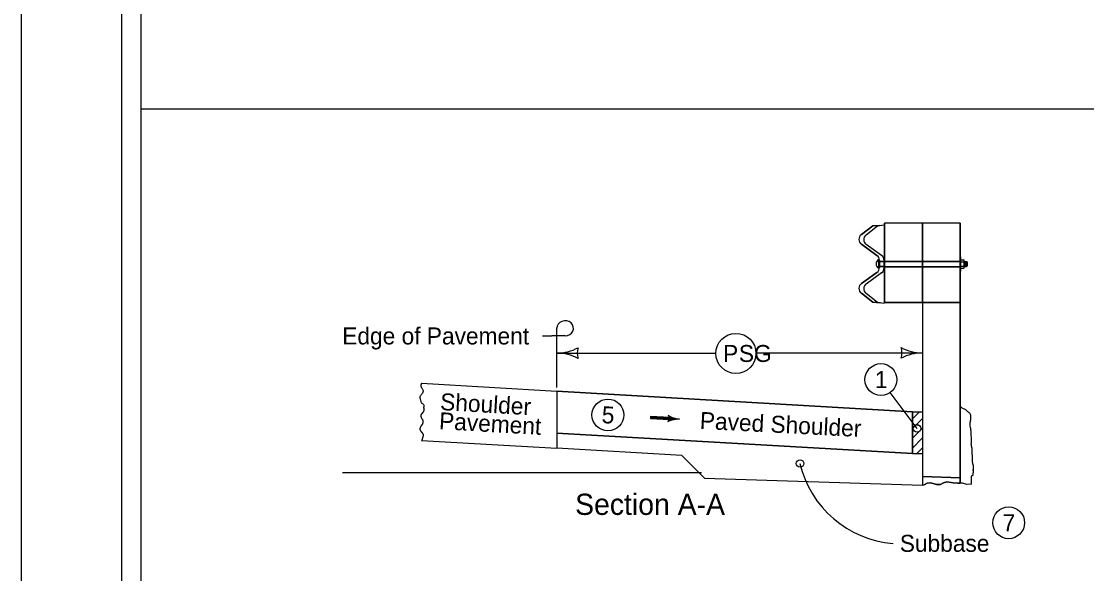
# Model space of a CAD drawing. Extents: x 10038 to 81668, y 7924 to 11018.
# Drawn here: x 10038 to 11041, y 8921 to 9442 of the extents above; entities that cross this region are included whole.
import ezdxf

# ---------------------------------------------------------------- set-up
doc = ezdxf.new("R2010")
doc.units = 0
for name, color, linetype in [('dsnCellElements', 7, 'Continuous'), ('DsnShtMinorGrid05', 7, 'Continuous'), ('DsnShtMinorGrid06', 7, 'Continuous'), ('DsnShtMinorGrid07', 7, 'Continuous'), ('DsnShtMinorGrid09', 7, 'Continuous'), ('DsnShtMinorGrid10', 7, 'Continuous'), ('DsnShtMinorGrid11', 7, 'Continuous'), ('DsnShtMinorGrid14', 7, 'Continuous'), ('Level 60', 7, 'Continuous'), ('SheetBorder', 7, 'Continuous')]:
    doc.layers.add(name, color=color, linetype=linetype)

msp = doc.modelspace()

# ---------------------------------------------------------------- linework, layer by layer
at = {"layer": 'dsnCellElements'}
msp.add_lwpolyline([(10037.7, 8180), (13358.6, 8180), (13358.6, 10373.4), (10037.7, 10373.4)], close=True, dxfattribs=at)
at = {"layer": 'DsnShtMinorGrid05'}
for p, q in [((10542.3, 9128.9), (10692.1, 9128.9)), ((10729.9, 9129), (10886.7, 9129))]:
    msp.add_line(p, q, dxfattribs=at)
msp.add_circle((10711, 9128.5), 18.9, dxfattribs=at)
for centre, radius, start, end in [((10542.3, 9171.4), 42.5, 270, 298.0725), ((10542.3, 9086.4), 42.5, 61.9275, 90), ((10577.9, 9128.9), 16.4, 162.2666, 197.7334), ((10851, 9129), 16.4, 342.2666, 17.7333), ((10886.7, 9171.5), 42.5, 241.9275, 270), ((10886.7, 9086.5), 42.5, 90, 118.0725), ((10866.6, 9047), 97.8, 193.077, 265.558)]:
    msp.add_arc(centre, radius, start, end, dxfattribs=at)
at = {"layer": 'DsnShtMinorGrid06'}
msp.add_line((10150.3, 9926.7), (10150.3, 8316.7), dxfattribs=at)
at = {"layer": 'DsnShtMinorGrid07'}
for p, q in [((10829.4, 9231.4), (10843.9, 9220.9)), ((10843.9, 9204.9), (10829.4, 9194.5))]:
    msp.add_line(p, q, dxfattribs=at)
for points in [[(10833.6, 9240.3), (10833.6, 9240.3), (10844.4, 9248.7), (10846.3, 9249), (10839.9, 9248.9), (10829.2, 9240.5)], [(10886.7, 9215.6), (10886.7, 9251.2), (10851.1, 9251.2), (10851.1, 9215.6), (10851.1, 9215.6), (10886.7, 9215.6)], [(10922.2, 9215.6), (10922.2, 9219.6), (10922.2, 9251.2), (10886.7, 9251.2), (10886.7, 9215.6), (10922.2, 9215.6)], [(10848.3, 9220.7), (10848.3, 9220.7), (10833.8, 9231.2), (10833.8, 9231.1)], [(10846.3, 9216.3), (10846.3, 9215.2), (10850.7, 9215.2), (10850.7, 9216.1), (10850.7, 9216.1)], [(10851.1, 9215.2), (10851.1, 9210.6), (10851.1, 9210.6), (10886.7, 9210.6), (10886.7, 9215.2), (10851.1, 9215.2), (10851.1, 9215.2)], [(10922.2, 9210.6), (10922.2, 9215.2), (10886.7, 9215.2), (10886.7, 9210.6), (10922.2, 9210.6)], [(10833.8, 9194.2), (10833.8, 9194.2), (10848.3, 9204.7), (10848.3, 9204.7)], [(10850.7, 9209.3), (10850.7, 9209.3), (10850.7, 9210.6), (10846.3, 9210.6), (10846.3, 9209.5), (10846.3, 9210.6), (10846.3, 9210.6), (10846.3, 9209.5)], [(10851.1, 9210.2), (10851.1, 9176.6), (10886.7, 9176.6), (10886.7, 9210.2), (10851.1, 9210.2)], [(10922.2, 9176.6), (10922.2, 9206.2), (10922.2, 9210.2), (10886.7, 9210.2), (10886.7, 9176.6), (10922.2, 9176.6)], [(10829.2, 9185.3), (10839.9, 9176.9), (10847, 9176.3), (10844.4, 9176.7), (10833.6, 9185.1), (10833.6, 9185.1)], [(10922.2, 9011.3), (10922.2, 9176.6), (10886.7, 9176.6), (10886.7, 9073.6), (10886.7, 9066.9), (10886.7, 9066.9), (10886.7, 9066.9), (10886.7, 9057.7), (10886.7, 9057.7), (10886.7, 9057.7), (10886.7, 9048.6), (10886.7, 9048.6), (10886.7, 9048.6), (10886.7, 9041.6), (10886.7, 9012.4), (10922.2, 9011.3)], [(10922.2, 9011.3), (10886.7, 9012.4), (10886.7, 9004.4), (10888.5, 9004.6), (10891.2, 9006.2), (10894.5, 9006.7), (10900.1, 9005.1), (10903.8, 9004.9), (10906.5, 9006.7), (10909.6, 9007.4), (10915.8, 9006.6), (10920, 9006.2), (10922.2, 9006.2), (10922.2, 9011.3)]]:
    msp.add_lwpolyline(points, dxfattribs=at)
msp.add_lwpolyline([(10850.7, 9215.2), (10846.3, 9215.2), (10846.3, 9211.8), (10846.3, 9212.9), (10846.3, 9210.6), (10850.7, 9210.6)], close=True, dxfattribs=at)
for centre, start, end in [((10832.6, 9236), 127.75, 234.6909), ((10837.1, 9235.8), 127.75, 234.6909), ((10840.6, 9216.3), 360, 54.691), ((10845, 9216.1), 360, 54.691), ((10840.6, 9209.5), 305.309, 0), ((10845, 9209.3), 305.309, 0), ((10832.6, 9189.8), 125.3091, 232.25), ((10837.1, 9189.6), 125.3091, 232.25)]:
    msp.add_arc(centre, 5.68, start, end, dxfattribs=at)
at = {"layer": 'DsnShtMinorGrid09'}
for centre, radius in [((10847.6, 9103.9), 15), ((10590.4, 9070.5), 15), ((10881.7, 9057.8), 3.58), ((10968, 8968.9), 15)]:
    msp.add_circle(centre, radius, dxfattribs=at)
at = {"layer": 'DsnShtMinorGrid10'}
for p, q in [((10528.9, 9145), (10537.6, 9145)), ((10550.1, 9145), (10537.6, 9145)), ((10542.3, 9132.2), (10542.3, 9153.1)), ((10542.3, 9096.3), (10542.3, 9132.2)), ((10648.6, 9067.2), (10630.4, 9068.2)), ((10648.5, 9066.2), (10648.5, 9066.2)), ((10648.7, 9068.2), (10648.7, 9068.2))]:
    msp.add_line(p, q, dxfattribs=at)
for points in [[(10648.7, 9068.1), (10630.5, 9069.1), (10630.4, 9067.3), (10648.5, 9066.2), (10648.6, 9067.8), (10630.7, 9068.9), (10630.7, 9067.4), (10648.2, 9066.5), (10648.3, 9067.6), (10631, 9068.7), (10630.9, 9067.7), (10647.9, 9066.7), (10648, 9067.4), (10631.1, 9068.4), (10631.1, 9067.9), (10647.7, 9066.9)], [(10648.3, 9069.4), (10649, 9068.2), (10648.9, 9066.5), (10648.2, 9065.1), (10650.9, 9066), (10654.1, 9066.7), (10655, 9066.8), (10652.8, 9067.3), (10649.6, 9068.6), (10648.6, 9069.1), (10648.7, 9065.6), (10653.7, 9066.8), (10649, 9068.4), (10649.1, 9066), (10652.5, 9066.9), (10649.5, 9067.8), (10649.2, 9066.4), (10651.4, 9066.9), (10649.8, 9067.4), (10649.7, 9066.7), (10650.4, 9066.9)]]:
    msp.add_lwpolyline(points, dxfattribs=at)
for centre, major_axis, start_param, end_param in [((10550.1, 9152.2), (-7.81, 0), 1.570796, 6.283185), ((10644.9, 9067.4), (3.88, 0), 5.202895, 7.237436), ((10657.1, 9046.4), (22.2, 0), 1.537172, 2.061295), ((10659.9, 9086.8), (-22.2, 0), 0.954258, 1.478381)]:
    msp.add_ellipse(centre, major_axis=major_axis, ratio=0.913811, start_param=start_param, end_param=end_param, dxfattribs=at)
at = {"layer": 'DsnShtMinorGrid11'}
for p, q in [((12305.9, 9358.7), (10150.3, 9358.7)), ((10881.7, 9057.8), (10856.3, 9091.7))]:
    msp.add_line(p, q, dxfattribs=at)
at = {"layer": 'DsnShtMinorGrid14'}
msp.add_circle((10771.4, 9024.8), 3.54, dxfattribs=at)
at = {"layer": 'Level 60'}
for p, q in [((10829.2, 9240.5), (10839.9, 9248.9)), ((10833.6, 9240.3), (10844.4, 9248.7)), ((10839.9, 9248.9), (10846.3, 9249)), ((10844.4, 9248.7), (10850.7, 9249.8)), ((10922.2, 9251.2), (10851.1, 9251.2)), ((10851.1, 9176.6), (10851.1, 9251.2)), ((10886.7, 9176.6), (10886.7, 9251.2)), ((10922.2, 9251.2), (10922.2, 9006.2)), ((10843.9, 9220.9), (10829.4, 9231.4)), ((10848.3, 9220.7), (10833.8, 9231.2)), ((10845.5, 9208.8), (10845.5, 9216.9)), ((10845.5, 9215.2), (10850.9, 9215.2)), ((10846.3, 9209.5), (10846.3, 9216.3)), ((10846.4, 9215.2), (10851.1, 9215.2)), ((10850.7, 9212.7), (10850.7, 9216.1)), ((10851.1, 9215.6), (10922.2, 9215.6)), ((10851.1, 9215.2), (10922.2, 9215.2)), ((10922.2, 9219.5), (10922.9, 9219.5)), ((10922.9, 9206.2), (10922.9, 9219.5)), ((10922.9, 9216.9), (10925.8, 9216.9)), ((10922.9, 9214.9), (10925.8, 9214.9)), ((10926.2, 9209.8), (10926.2, 9215.9)), ((10926.2, 9215.2), (10928.6, 9215.2)), ((10927.1, 9215.2), (10927.1, 9210.5)), ((10927.8, 9215.2), (10927.8, 9210.5)), ((10928.6, 9215.2), (10929, 9214.7)), ((10928.6, 9215.2), (10928.6, 9210.5)), ((10929, 9214.7), (10929, 9211.1)), ((10829.4, 9194.5), (10843.9, 9204.9)), ((10833.8, 9194.2), (10848.3, 9204.7)), ((10845.5, 9210.6), (10851.1, 9210.6)), ((10846.3, 9209.5), (10846.3, 9212.9)), ((10846.3, 9212.9), (10846.3, 9209.5)), ((10850.7, 9209.3), (10850.7, 9212.7)), ((10850.7, 9212.7), (10850.7, 9209.3)), ((10851.1, 9210.6), (10922.2, 9210.6)), ((10851.1, 9210.2), (10922.2, 9210.2)), ((10922.2, 9206.2), (10922.9, 9206.2)), ((10922.9, 9210.9), (10925.8, 9210.9)), ((10922.9, 9208.8), (10925.8, 9208.8)), ((10926.2, 9210.5), (10928.6, 9210.5)), ((10929, 9211.1), (10928.6, 9210.5)), ((10839.9, 9176.9), (10829.2, 9185.3)), ((10844.4, 9176.7), (10833.6, 9185.1)), ((10847, 9176.3), (10839.9, 9176.9)), ((10850.7, 9175.6), (10844.4, 9176.7)), ((10886.7, 9176.6), (10851.1, 9176.6)), ((10886.7, 9176.6), (10886.7, 9004.4)), ((10414.8, 9100.5), (10542.3, 9093.1)), ((10542.3, 9093.1), (10542.3, 9039.1)), ((10542.3, 9093.1), (10877.4, 9073.6)), ((10877.4, 9073.6), (10542.3, 9093.1)), ((10542.3, 9093.1), (10542.3, 9053.5)), ((10877.4, 9066.9), (10884.1, 9073.6)), ((10877.4, 9066.9), (10884.1, 9073.6)), ((10877.4, 9066.9), (10884.1, 9073.6)), ((10877.4, 9066.9), (10884.1, 9073.6)), ((10877.4, 9073.6), (10886.6, 9073.6)), ((10877.4, 9073.6), (10877.4, 9034.2)), ((10877.4, 9034.2), (10877.4, 9073.6)), ((10877.4, 9057.7), (10886.6, 9066.9)), ((10877.4, 9057.7), (10886.6, 9066.9)), ((10877.4, 9057.7), (10886.6, 9066.9)), ((10877.4, 9057.7), (10886.6, 9066.9)), ((10932.2, 9066.9), (10932.2, 9066.9)), ((10877.4, 9048.5), (10886.6, 9057.7)), ((10877.4, 9048.5), (10886.6, 9057.7)), ((10877.4, 9048.5), (10886.6, 9057.7)), ((10877.4, 9048.5), (10886.6, 9057.7)), ((10414.8, 9046.5), (10542.3, 9039.1)), ((10877.4, 9034.2), (10542.3, 9053.5)), ((10542.3, 9053.5), (10877.4, 9034.2)), ((10877.4, 9039.2), (10886.6, 9048.5)), ((10660.1, 9032.3), (10542.3, 9039.1)), ((10877.4, 9034.2), (10886.6, 9034.2)), ((10881.5, 9034.2), (10886.6, 9039.3)), ((10660.1, 9032.3), (10681.4, 9011.1)), ((10340.2, 9016.3), (10678.7, 9016.3)), ((10681.4, 9011.1), (10886.7, 9004.4))]:
    msp.add_line(p, q, dxfattribs=at)
for points in [[(10925.9, 9214.9), (10926, 9214.9), (10926.1, 9215), (10926.1, 9215.3), (10926.2, 9215.6), (10926.2, 9213.6), (10926.1, 9214.1), (10926.1, 9214.5), (10926, 9214.8), (10925.9, 9214.9), (10926, 9214.9), (10926.1, 9215.1), (10926.2, 9215.3), (10926.2, 9215.4), (10926.2, 9213.9), (10926.1, 9214.4), (10926.1, 9214.7), (10925.9, 9214.9), (10926, 9214.9), (10926.1, 9215.1), (10926.2, 9215.3), (10926.2, 9214.2), (10926, 9214.9), (10926.1, 9215.1), (10926.1, 9214.3), (10926, 9214.9), (10926.1, 9215.1), (10926.1, 9214.4), (10926, 9214.8), (10926.1, 9215), (10926.1, 9214.6), (10926, 9214.8), (10926.1, 9214.9), (10926.1, 9214.7), (10926.1, 9214.8), (10926.1, 9214.9)], [(10926.2, 9210.2), (10926.2, 9210.4), (10926.1, 9210.6), (10926, 9210.8), (10925.9, 9210.9), (10926, 9211), (10926.1, 9211.2), (10926.1, 9211.5), (10926.2, 9212.2), (10926.2, 9210.2), (10926.2, 9210.3), (10926.1, 9210.5), (10926.1, 9210.7), (10925.9, 9210.8), (10926, 9210.9), (10926, 9211.1), (10926.1, 9211.6), (10926.2, 9212), (10926.2, 9210.4), (10926.2, 9210.5), (10926.1, 9210.6), (10926, 9210.8), (10926, 9211), (10926.1, 9211.3), (10926.2, 9211.7), (10926.2, 9210.5), (10926.1, 9210.6), (10926, 9210.8), (10926, 9211.1), (10926.1, 9211.3), (10926.1, 9211.5), (10926.1, 9210.6), (10926.1, 9210.7), (10926, 9210.8), (10926.1, 9211.3), (10926.1, 9210.7), (10926, 9210.8), (10926.1, 9211.1), (10926.1, 9210.8), (10926.1, 9210.8), (10926.1, 9210.9), (10926.1, 9210.9)], [(10932.7, 9043), (10932.7, 9042.7), (10932.7, 9042.6), (10932.7, 9042.4), (10932.7, 9042.2), (10932.7, 9042), (10932.7, 9041.8), (10932.7, 9041.5), (10932.7, 9041.3), (10932.8, 9041), (10932.9, 9040.7), (10933.1, 9040.5), (10933.1, 9040.3), (10933.1, 9040.1), (10933.1, 9039.9), (10933.1, 9039.7), (10933.2, 9039.6), (10933.2, 9039.4), (10933.2, 9039.2), (10933.2, 9039), (10933.2, 9038.8), (10933.2, 9038.6), (10933.2, 9038.4), (10933.2, 9038.1), (10933.2, 9037.9), (10933.2, 9037.6), (10933.2, 9037.4), (10933.2, 9037.2), (10933.3, 9037.1), (10933.3, 9036.9), (10933.3, 9036.7), (10933.3, 9036.5), (10933.3, 9036.3), (10933.3, 9036.1), (10933.3, 9035.9), (10933.3, 9035.7), (10933.3, 9035.5), (10933.3, 9035.3), (10933.3, 9035.1), (10933.3, 9034.9), (10933.3, 9034.7), (10933.3, 9034.5), (10933.3, 9034.3), (10933.3, 9034.2), (10933.3, 9034), (10933.3, 9033.8), (10933.3, 9033.6), (10933.4, 9033.5), (10933.4, 9033.3), (10933.4, 9033.1), (10933.5, 9033), (10933.5, 9032.8), (10933.5, 9032.6), (10933.6, 9032.5), (10933.6, 9032.3), (10933.6, 9032.1), (10933.6, 9031.9), (10933.6, 9031.6), (10933.7, 9031.3), (10933.7, 9031.1), (10933.7, 9030.9), (10933.7, 9030.7), (10933.7, 9030.5), (10933.7, 9030.3), (10933.7, 9030.1), (10933.7, 9030), (10933.7, 9029.8), (10933.7, 9029.6), (10933.7, 9029.4), (10933.7, 9029.2), (10933.7, 9029), (10933.7, 9028.8), (10933.7, 9028.6), (10933.7, 9028.4), (10933.7, 9028.2), (10933.7, 9028), (10933.7, 9027.8), (10933.7, 9027.6), (10933.7, 9027.4), (10933.7, 9027.2), (10933.7, 9027), (10933.7, 9026.8), (10933.7, 9026.6), (10933.7, 9026.4), (10933.7, 9026.2), (10933.7, 9026), (10933.7, 9025.8), (10933.7, 9025.7), (10933.8, 9025.6), (10933.8, 9025.3), (10933.8, 9025.1), (10933.9, 9024.9), (10934, 9024.6), (10934, 9024.4), (10934.1, 9024.3), (10934.1, 9024.1), (10934.2, 9024), (10934.3, 9023.9), (10934.3, 9023.7), (10934.3, 9023.5), (10934.3, 9023.3), (10934.4, 9023.2), (10934.4, 9023), (10934.4, 9022.8), (10934.4, 9022.6), (10934.4, 9022.4), (10934.4, 9022.2), (10934.4, 9022), (10934.4, 9021.8), (10934.4, 9021.6), (10934.4, 9021.5), (10934.4, 9021.3), (10934.4, 9021.1), (10934.4, 9020.9), (10934.4, 9020.7), (10934.4, 9020.5), (10934.4, 9020.3), (10934.4, 9020.1), (10934.4, 9019.9), (10934.4, 9019.7), (10934.4, 9019.5), (10934.4, 9019.3), (10934.4, 9019.1), (10934.4, 9018.9), (10934.4, 9018.7), (10934.4, 9018.5), (10934.4, 9018.3), (10934.4, 9018.3), (10934.4, 9018.6), (10934.4, 9018.8), (10934.4, 9019), (10934.4, 9018.8), (10934.4, 9018.6), (10934.4, 9018.4), (10934.4, 9018.2), (10934.4, 9018), (10934.4, 9017.8), (10934.4, 9017.6), (10934.4, 9017.4), (10934.4, 9017.2), (10934.4, 9017.1), (10934.4, 9016.9), (10934.4, 9016.7), (10934.4, 9016.5), (10934.4, 9016.3), (10934.4, 9016.1), (10934.3, 9016), (10934.3, 9015.8), (10934.3, 9015.6), (10934.3, 9015.4), (10934.3, 9015.2), (10934.3, 9015), (10934.3, 9014.8), (10934.3, 9014.6), (10934.3, 9014.4), (10934.3, 9014.2), (10934.3, 9014), (10934.2, 9013.9), (10934.1, 9013.7), (10934, 9013.6), (10933.9, 9013.5), (10933.8, 9013.4), (10933.6, 9013.3), (10933.4, 9013.3), (10933.3, 9013.2), (10933.2, 9013.1), (10933.1, 9013), (10933, 9013), (10932.9, 9012.9), (10932.9, 9012.7), (10932.8, 9012.6), (10932.8, 9012.4), (10932.8, 9012.2), (10932.8, 9012), (10932.8, 9005.2)], [(10932.9, 9005.2), (10928.7, 9005), (10924.6, 9006.2), (10920, 9006.2), (10915.8, 9006.6), (10909.6, 9007.4), (10906.5, 9006.7), (10903.8, 9004.9), (10900.1, 9005.1), (10894.5, 9006.7), (10891.2, 9006.2), (10888.5, 9004.6), (10886.7, 9004.4)]]:
    msp.add_lwpolyline(points, dxfattribs=at)
msp.add_circle((10590.4, 9070.5), 15, dxfattribs=at)
for centre, radius, start, end in [((10832.6, 9236), 5.68, 127.75, 234.6909), ((10837.1, 9235.8), 5.68, 127.75, 234.6909), ((10847.6, 9212.9), 4.54, 117.2029, 242.8461), ((10840.6, 9216.3), 5.68, 360, 54.691), ((10845, 9216.1), 5.68, 360, 54.691), ((10840.6, 9209.5), 5.68, 305.309, 0), ((10845, 9209.3), 5.68, 305.309, 0), ((10832.6, 9189.8), 5.68, 125.3091, 232.25), ((10837.1, 9189.6), 5.68, 125.3091, 232.25)]:
    msp.add_arc(centre, radius, start, end, dxfattribs=at)
for centre in [(10925.8, 9215.9), (10925.8, 9209.8)]:
    msp.add_ellipse(centre, major_axis=(0, -1.01), ratio=0.362258, start_param=6.283156, end_param=9.424748, dxfattribs=at)
for points in [[(10414.8, 9100.5), (10414.3, 9096.9), (10415.3, 9095.4), (10416.2, 9093.1), (10415.6, 9091.1), (10413.7, 9088.7), (10413.2, 9086.8), (10413.7, 9084.5), (10414.6, 9082.1), (10415.6, 9081.4), (10417, 9078.9), (10417, 9078)], [(10415, 9060.9), (10415.2, 9061.2), (10415.4, 9061.4), (10415.8, 9062), (10416, 9062.6), (10416.2, 9062.9), (10416.3, 9063.2), (10416.4, 9063.8), (10416.4, 9064.4), (10416.4, 9065), (10416.3, 9065.3), (10416.3, 9065.4), (10416.3, 9065.6), (10416, 9065.9), (10415.8, 9066.3), (10415.5, 9066.7), (10415.2, 9067.1), (10415.1, 9067.4), (10414.9, 9067.6), (10414.7, 9068.2), (10414.5, 9068.8), (10414.4, 9069.1), (10414.4, 9069.4), (10414.3, 9069.5), (10414.3, 9069.6), (10414.5, 9070.4), (10414.7, 9070.9), (10415, 9071.4), (10415.4, 9072.1), (10415.9, 9072.6), (10416.4, 9073.2), (10416.7, 9073.5), (10416.9, 9073.8), (10417.1, 9074.3), (10417.2, 9074.8), (10417.3, 9075.2), (10417.4, 9075.5), (10417.4, 9075.6), (10417.4, 9075.7), (10417.3, 9076.2), (10417.2, 9076.7), (10417.1, 9076.9), (10417.1, 9077), (10417, 9077.1), (10417, 9077.2), (10417, 9078)], [(10932.7, 9043), (10933, 9045.9), (10932.8, 9050.8), (10932.4, 9056.5), (10931.7, 9061), (10931.9, 9064.3), (10932.4, 9068.5), (10931.7, 9071.6), (10929.5, 9073.6), (10927.5, 9075.3), (10925.3, 9076.4), (10923.1, 9077.8), (10922.2, 9078.4)], [(10415, 9060.9), (10414.8, 9060.7), (10414.5, 9060.5), (10414.3, 9060.2), (10414.1, 9059.9), (10414, 9059.7), (10413.8, 9059.4), (10413.6, 9058.8), (10413.5, 9058.5), (10413.4, 9058.2), (10413.3, 9057.9), (10413.3, 9057.8), (10413.3, 9057.6), (10413.3, 9057.1), (10413.4, 9056.6), (10413.6, 9056.1), (10413.9, 9055.6), (10414.3, 9054.9), (10414.8, 9054.4), (10415.3, 9053.9), (10415.6, 9053.5), (10415.8, 9053.2), (10416.2, 9052.3), (10416.3, 9051.8), (10416.3, 9051.3), (10416.3, 9051), (10416.2, 9050.7), (10416.2, 9050.4), (10416.1, 9050.2), (10415.8, 9049), (10415.6, 9048.4), (10415.4, 9047.8), (10415.2, 9047.2), (10415, 9046.9), (10414.9, 9046.6), (10414.8, 9046.5)]]:
    msp.add_spline(points, degree=3, dxfattribs=at)
at = {"layer": 'SheetBorder'}
msp.add_lwpolyline([(10132.5, 9944), (13267.5, 9944), (13267.5, 7924), (10132.5, 7924)], close=True, dxfattribs=at)

# ---------------------------------------------------------------- texts
at = {"layer": 'DsnShtMinorGrid05'}
for s, p in [('P', (10698.9, 9120.5)), ('SG', (10713.8, 9120.5))]:
    msp.add_text(s, height=16, dxfattribs=at).set_placement(p)
at = {"layer": 'DsnShtMinorGrid09'}
for s, p in [('1', (10842, 9095.9)), ('7', (10962.3, 8960.9))]:
    msp.add_text(s, height=16, dxfattribs=at).set_placement(p)
msp.add_text('5', height=16, rotation=356.6997, dxfattribs=at).set_placement((10584.2, 9062.9))
at = {"layer": 'DsnShtMinorGrid10'}
for s, height, p in [('Edge of Pavement', 16, (10340.1, 9137)), ('Section A-A', 20, (10559.5, 8976.3)), ('Subbase', 16, (10865.4, 8941.5))]:
    msp.add_text(s, height=height, dxfattribs=at).set_placement(p)
for s, rotation, p in [('Shoulder', 356.7346, (10432, 9075.2)), ('Pavement', 356.7346, (10431, 9057.2)), ('Paved Shoulder ', 357.0678, (10676.7, 9057.5))]:
    msp.add_text(s, height=16, rotation=rotation, dxfattribs=at).set_placement(p)

doc.saveas('drawing.dxf')
